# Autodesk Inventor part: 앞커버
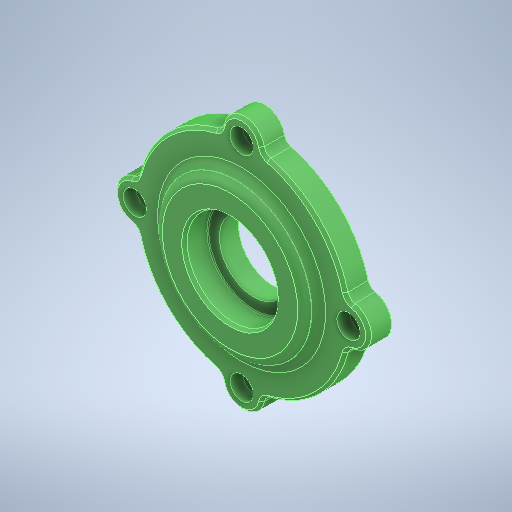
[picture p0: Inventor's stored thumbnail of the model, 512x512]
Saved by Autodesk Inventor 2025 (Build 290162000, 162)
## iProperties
Created: 2024-08
Part Number: 앞커버
Material: 알루미늄 6061
Document SubType Name: Modeling
Designer: onair
Density: 2.71 g/cm^3
Appearance: 기본값
Company: 한국ATC센터
Author: jhkim
Sending System: Autodesk Inventor 2025
Preprocessor: ST-DEVELOPER v20
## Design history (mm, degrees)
feature "솔리드1"
node "솔리드2"
